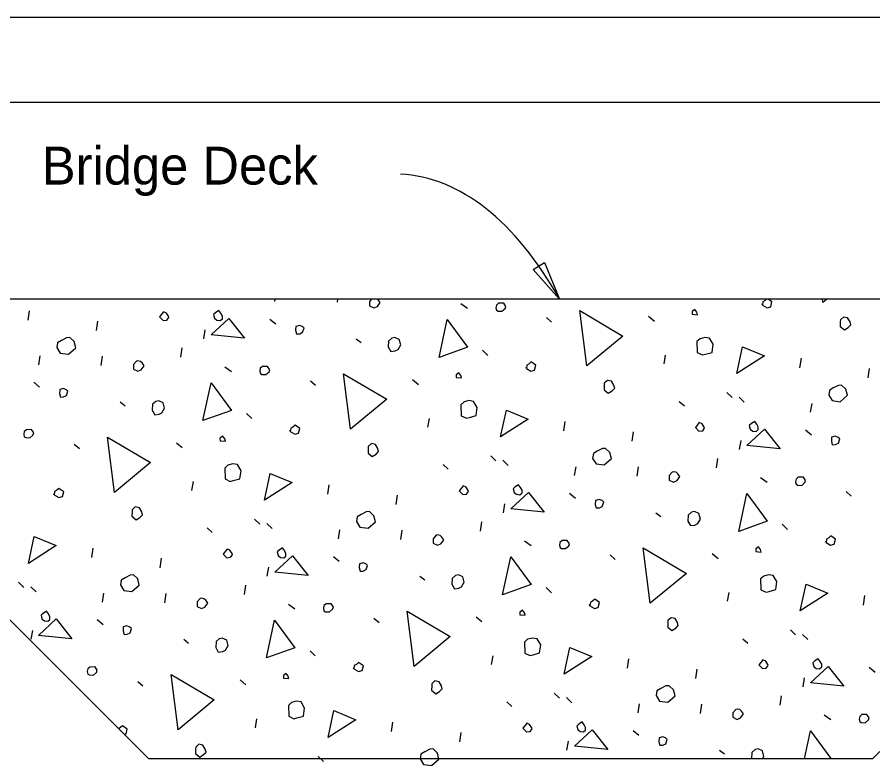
# Model space of a CAD drawing. Extents: x 0 to 30.8, y 0 to 21.2.
# Drawn here: x 22.102 to 25.516, y 16.841 to 19.8 of the extents above; entities that cross this region are included whole.
import ezdxf

# ---------------------------------------------------------------- set-up
doc = ezdxf.new("R2010")
doc.units = 0
for name, color, linetype in [('ActivePts-ConstElements', 7, 'Continuous'), ('Dimension', 7, 'Continuous'), ('Miscellaneous', 7, 'Continuous'), ('Miscellaneous1', 7, 'Continuous'), ('SupstrConc', 7, 'Continuous'), ('TextStructures', 7, 'Continuous')]:
    doc.layers.add(name, color=color, linetype=linetype)

msp = doc.modelspace()

# ---------------------------------------------------------------- linework, layer by layer
at = {"layer": 'ActivePts-ConstElements'}
msp.add_lwpolyline([(0, 0), (30.7879, 0), (30.7879, 19.4596), (0, 19.4596)], close=True, dxfattribs=at)
at = {"layer": 'Dimension'}
msp.add_lwpolyline([(24.2661, 18.6746), (24.1614, 18.7936), (24.2064, 18.8214)], close=True, dxfattribs=at)
msp.add_ellipse((23.5209, 16.8059), major_axis=(-0.1111, -2.3674), ratio=0.464296, start_param=2.502126, end_param=3.141581, dxfattribs=at)
at = {"layer": 'Miscellaneous'}
for p, q in [((23.1306, 18.6659), (23.1321, 18.6747)), ((23.3799, 18.6628), (23.3816, 18.6747)), ((23.873, 18.6577), (23.8988, 18.6388)), ((22.1464, 18.5911), (22.1518, 18.6288)), ((24.6216, 18.6073), (24.6449, 18.5876)), ((22.4188, 18.5502), (22.4242, 18.5879)), ((23.1105, 18.5958), (23.1339, 18.5762)), ((24.2141, 18.6016), (24.2345, 18.5838)), ((22.8469, 18.5174), (22.8529, 18.5526)), ((23.4551, 18.5173), (23.4748, 18.5019)), ((22.7553, 18.4437), (22.7607, 18.4814)), ((23.9592, 18.4712), (23.9802, 18.4509)), ((22.1888, 18.4135), (22.1949, 18.4488)), ((22.4381, 18.4104), (22.4435, 18.4481)), ((24.683, 18.4167), (24.6891, 18.4519)), ((25.2254, 18.4015), (25.2308, 18.4392)), ((22.9312, 18.4054), (22.957, 18.3864)), ((25.4978, 18.3606), (25.5032, 18.3983)), ((22.1688, 18.3434), (22.1921, 18.3238)), ((23.2724, 18.3493), (23.2927, 18.3314)), ((23.6798, 18.3549), (23.7032, 18.3353)), ((24.9335, 18.3026), (24.9545, 18.2824)), ((22.5133, 18.2649), (22.533, 18.2495)), ((24.7437, 18.2673), (24.764, 18.2494)), ((24.9824, 18.2846), (25.0033, 18.2644)), ((25.2678, 18.224), (25.2739, 18.2592)), ((23.0174, 18.2188), (23.0384, 18.1986)), ((23.7412, 18.1643), (23.7473, 18.1996)), ((24.2836, 18.1492), (24.289, 18.1869)), ((24.556, 18.1083), (24.5614, 18.146)), ((25.2477, 18.1539), (25.2711, 18.1343)), ((22.3306, 18.0969), (22.3509, 18.0791)), ((22.738, 18.1026), (22.7614, 18.0829)), ((24.9841, 18.0755), (24.9901, 18.1107)), ((23.9918, 18.0503), (24.0127, 18.03)), ((24.0406, 18.0323), (24.0615, 18.012)), ((24.8925, 18.0018), (24.8979, 18.0394)), ((23.8019, 18.0149), (23.8223, 17.9971)), ((24.326, 17.9716), (24.3321, 18.0069)), ((24.5753, 17.9685), (24.5807, 18.0062)), ((25.0684, 17.9635), (25.0942, 17.9445)), ((22.7994, 17.912), (22.8055, 17.9472)), ((23.3418, 17.8968), (23.3473, 17.9345)), ((23.6142, 17.8559), (23.6196, 17.8936)), ((24.306, 17.9015), (24.3293, 17.8819)), ((25.4096, 17.9074), (25.4299, 17.8895)), ((24.0423, 17.8231), (24.0484, 17.8584)), ((24.6505, 17.823), (24.6702, 17.8076)), ((23.05, 17.7979), (23.0709, 17.7777)), ((23.9507, 17.7494), (23.9562, 17.7871)), ((22.8602, 17.7626), (22.8805, 17.7447)), ((23.0988, 17.7799), (23.1198, 17.7597)), ((23.3842, 17.7193), (23.3903, 17.7545)), ((23.6335, 17.7162), (23.639, 17.7539)), ((25.1546, 17.7769), (25.1756, 17.7567)), ((24.1266, 17.7111), (24.1524, 17.6922)), ((22.4001, 17.6445), (22.4055, 17.6822)), ((23.3642, 17.6492), (23.3876, 17.6296)), ((24.4678, 17.655), (24.4881, 17.6372)), ((24.8752, 17.6607), (24.8986, 17.641)), ((22.6724, 17.6036), (22.6778, 17.6413)), ((23.1005, 17.5708), (23.1066, 17.606)), ((23.7087, 17.5707), (23.7284, 17.5552)), ((22.1082, 17.5456), (22.1292, 17.5253)), ((22.157, 17.5276), (22.178, 17.5073)), ((23.009, 17.4971), (23.0144, 17.5347)), ((24.2129, 17.5246), (24.2338, 17.5043)), ((22.4425, 17.4669), (22.4485, 17.5022)), ((22.6918, 17.4638), (22.6972, 17.5015)), ((24.9366, 17.4701), (24.9427, 17.5053)), ((25.479, 17.4549), (25.4845, 17.4926)), ((23.1849, 17.4588), (23.2106, 17.4398)), ((22.4224, 17.3968), (22.4458, 17.3772)), ((23.526, 17.4027), (23.5463, 17.3848)), ((23.9334, 17.4083), (23.9568, 17.3887)), ((22.1587, 17.3184), (22.1648, 17.3537)), ((25.1872, 17.356), (25.2081, 17.3358)), ((22.767, 17.3183), (22.7866, 17.3029)), ((24.9974, 17.3207), (25.0177, 17.3028)), ((25.236, 17.338), (25.257, 17.3178)), ((23.2711, 17.2722), (23.292, 17.252)), ((23.9949, 17.2177), (24.0009, 17.253)), ((24.5373, 17.2026), (24.5427, 17.2403)), ((25.5014, 17.2073), (25.5248, 17.1877)), ((24.8096, 17.1617), (24.815, 17.1994)), ((22.5842, 17.1503), (22.6045, 17.1325)), ((22.9917, 17.156), (23.015, 17.1363)), ((25.2377, 17.1289), (25.2438, 17.1641)), ((24.2454, 17.1037), (24.2664, 17.0834)), ((24.2942, 17.0857), (24.3152, 17.0654)), ((25.1462, 17.0551), (25.1516, 17.0928)), ((24.0556, 17.0683), (24.0759, 17.0505)), ((24.5797, 17.025), (24.5857, 17.0603)), ((24.8289, 17.0219), (24.8344, 17.0596)), ((23.0531, 16.9654), (23.0592, 17.0006)), ((25.3221, 17.0169), (25.3478, 16.9979)), ((23.5955, 16.9502), (23.6009, 16.9879)), ((23.8678, 16.9093), (23.8733, 16.947)), ((24.5596, 16.9549), (24.583, 16.9353)), ((24.2959, 16.8765), (24.302, 16.9118)), ((24.9042, 16.8764), (24.9238, 16.861)), ((23.3036, 16.8513), (23.3246, 16.8311))]:
    msp.add_line(p, q, dxfattribs=at)
for points in [[(23.5084, 18.6662), (23.5081, 18.648), (23.5258, 18.6398), (23.5397, 18.6461), (23.5509, 18.662), (23.5428, 18.6728), (23.5406, 18.6747)], [(23.5159, 18.6747), (23.5084, 18.6662)], [(25.092, 18.6747), (25.0862, 18.6697), (25.0772, 18.6647), (25.0756, 18.6513), (25.0743, 18.6561)], [(25.0756, 18.6513), (25.094, 18.6407), (25.1085, 18.6446), (25.1136, 18.6641), (25.098, 18.6747)], [(25.3162, 18.6614), (25.3145, 18.6747)], [(25.3324, 18.6747), (25.3162, 18.6614)], [(24.0147, 18.631), (24.0209, 18.6275), (24.0366, 18.6265), (24.0492, 18.6377), (24.0521, 18.6462), (24.0434, 18.6594), (24.0228, 18.659), (24.0144, 18.6516), (24.0122, 18.6407), (24.0147, 18.631)], [(22.6707, 18.6048), (22.6849, 18.5904), (22.7001, 18.5919), (22.7078, 18.6017), (22.7065, 18.6066), (22.6978, 18.6198), (22.6862, 18.6244), (22.6785, 18.6146), (22.6707, 18.6048)], [(22.8898, 18.5987), (22.8996, 18.591), (22.913, 18.5894), (22.9213, 18.5968), (22.9212, 18.6072), (22.9155, 18.6186), (22.9074, 18.6294), (22.8942, 18.6207), (22.8859, 18.6132), (22.8898, 18.5987)], [(24.3744, 18.409), (24.3465, 18.6293), (24.5186, 18.5279), (24.3744, 18.409)], [(24.7955, 18.615), (24.8167, 18.613), (24.8141, 18.6226), (24.8061, 18.6334), (24.7953, 18.6253), (24.7955, 18.615)], [(22.8763, 18.533), (22.9468, 18.5985), (23.0093, 18.5195), (22.8763, 18.533)], [(23.7856, 18.4428), (23.8177, 18.5937), (23.899, 18.4835), (23.7856, 18.4428)], [(25.386, 18.5843), (25.3857, 18.5661), (25.4023, 18.5525), (25.418, 18.5618), (25.4281, 18.5723), (25.4249, 18.5844), (25.4155, 18.6), (25.3991, 18.6034), (25.3865, 18.5922), (25.386, 18.5843)], [(23.2132, 18.5508), (23.2171, 18.5363), (23.2298, 18.5372), (23.2412, 18.5428), (23.247, 18.5599), (23.2402, 18.5658), (23.2286, 18.5705), (23.2141, 18.5666), (23.2132, 18.5508)], [(22.261, 18.482), (22.2748, 18.4598), (22.307, 18.4555), (22.3362, 18.4815), (22.3298, 18.5056), (22.3125, 18.5217), (22.2998, 18.5209), (22.2794, 18.5102), (22.2638, 18.5009), (22.261, 18.482)], [(23.5844, 18.5079), (23.583, 18.4843), (23.593, 18.4662), (23.6106, 18.4684), (23.622, 18.474), (23.6326, 18.4924), (23.6268, 18.5141), (23.6091, 18.5223), (23.597, 18.5191), (23.5844, 18.5079)], [(24.8143, 18.5062), (24.8156, 18.4626), (24.8364, 18.4526), (24.8485, 18.4558), (24.8751, 18.4629), (24.8794, 18.4952), (24.865, 18.5198), (24.8462, 18.5225), (24.8268, 18.5173), (24.8143, 18.5062)], [(24.9729, 18.3779), (24.996, 18.485), (25.0833, 18.4489), (24.9729, 18.3779)], [(22.5666, 18.4138), (22.5663, 18.3956), (22.584, 18.3874), (22.5979, 18.3937), (22.6091, 18.4097), (22.6011, 18.4205), (22.5943, 18.4264), (22.5833, 18.4286), (22.5785, 18.4273), (22.5666, 18.4138)], [(23.073, 18.3787), (23.0791, 18.3751), (23.0949, 18.3742), (23.1074, 18.3853), (23.1103, 18.3938), (23.1016, 18.407), (23.081, 18.4067), (23.0726, 18.3993), (23.0704, 18.3883), (23.073, 18.3787)], [(24.1339, 18.3989), (24.1522, 18.3883), (24.1667, 18.3922), (24.1719, 18.4117), (24.1528, 18.4247), (24.1445, 18.4173), (24.1355, 18.4123), (24.1339, 18.3989), (24.1326, 18.4038)], [(23.4327, 18.1567), (23.4047, 18.377), (23.5768, 18.2756), (23.4327, 18.1567)], [(23.8537, 18.3627), (23.875, 18.3606), (23.8724, 18.3703), (23.8643, 18.3811), (23.8535, 18.373), (23.8537, 18.3627)], [(22.8439, 18.1905), (22.8759, 18.3414), (22.9572, 18.2312), (22.8439, 18.1905)], [(24.4443, 18.332), (24.444, 18.3138), (24.4606, 18.3001), (24.4762, 18.3095), (24.4863, 18.32), (24.4831, 18.332), (24.4737, 18.3476), (24.4573, 18.351), (24.4447, 18.3399), (24.4443, 18.332)], [(25.34, 18.2925), (25.3537, 18.2703), (25.3859, 18.266), (25.4152, 18.2919), (25.4088, 18.3161), (25.3915, 18.3322), (25.3788, 18.3313), (25.3583, 18.3207), (25.3427, 18.3113), (25.34, 18.2925)], [(22.2714, 18.2985), (22.2753, 18.284), (22.288, 18.2848), (22.2994, 18.2905), (22.3052, 18.3075), (22.2984, 18.3135), (22.2868, 18.3181), (22.2724, 18.3143), (22.2714, 18.2985)], [(22.6427, 18.2556), (22.6412, 18.2319), (22.6512, 18.2139), (22.6688, 18.216), (22.6802, 18.2217), (22.6908, 18.24), (22.685, 18.2618), (22.6673, 18.27), (22.6552, 18.2667), (22.6427, 18.2556)], [(23.8725, 18.2538), (23.8739, 18.2102), (23.8946, 18.2002), (23.9067, 18.2035), (23.9333, 18.2106), (23.9376, 18.2428), (23.9232, 18.2674), (23.9044, 18.2702), (23.8851, 18.265), (23.8725, 18.2538)], [(24.0311, 18.1255), (24.0542, 18.2326), (24.1415, 18.1965), (24.0311, 18.1255)], [(23.1921, 18.1466), (23.2105, 18.136), (23.2249, 18.1399), (23.2301, 18.1594), (23.2111, 18.1724), (23.2027, 18.165), (23.1937, 18.16), (23.1921, 18.1466), (23.1908, 18.1514)], [(24.8079, 18.1629), (24.8221, 18.1485), (24.8373, 18.15), (24.845, 18.1598), (24.8437, 18.1647), (24.835, 18.1779), (24.8234, 18.1825), (24.8157, 18.1727), (24.8079, 18.1629)], [(25.027, 18.1568), (25.0368, 18.1491), (25.0502, 18.1475), (25.0585, 18.1549), (25.0583, 18.1652), (25.0527, 18.1767), (25.0446, 18.1875), (25.0314, 18.1787), (25.0231, 18.1713), (25.027, 18.1568)], [(22.1312, 18.1263), (22.1373, 18.1228), (22.1531, 18.1218), (22.1656, 18.133), (22.1685, 18.1415), (22.1598, 18.1547), (22.1392, 18.1543), (22.1308, 18.1469), (22.1286, 18.136), (22.1312, 18.1263)], [(22.9119, 18.1103), (22.9332, 18.1083), (22.9306, 18.1179), (22.9225, 18.1287), (22.9117, 18.1206), (22.9119, 18.1103)], [(25.0135, 18.0911), (25.084, 18.1566), (25.1465, 18.0776), (25.0135, 18.0911)], [(25.3504, 18.1089), (25.3543, 18.0944), (25.367, 18.0952), (25.3784, 18.1009), (25.3842, 18.118), (25.3774, 18.1239), (25.3658, 18.1286), (25.3513, 18.1247), (25.3504, 18.1089)], [(22.4909, 17.9043), (22.4629, 18.1246), (22.635, 18.0232), (22.4909, 17.9043)], [(23.5025, 18.0796), (23.5022, 18.0614), (23.5188, 18.0478), (23.5344, 18.0571), (23.5445, 18.0676), (23.5413, 18.0797), (23.5319, 18.0953), (23.5155, 18.0987), (23.503, 18.0875), (23.5025, 18.0796)], [(24.3982, 18.0401), (24.412, 18.0179), (24.4442, 18.0136), (24.4734, 18.0396), (24.467, 18.0637), (24.4497, 18.0798), (24.437, 18.079), (24.4166, 18.0683), (24.401, 18.059), (24.3982, 18.0401)], [(22.9307, 18.0015), (22.9321, 17.9579), (22.9529, 17.9479), (22.9649, 17.9511), (22.9915, 17.9583), (22.9958, 17.9905), (22.9814, 18.0151), (22.9626, 18.0178), (22.9433, 18.0126), (22.9307, 18.0015)], [(23.0893, 17.8732), (23.1124, 17.9803), (23.1997, 17.9442), (23.0893, 17.8732)], [(24.7038, 17.9719), (24.7035, 17.9537), (24.7212, 17.9455), (24.7351, 17.9518), (24.7463, 17.9678), (24.7383, 17.9785), (24.7315, 17.9845), (24.7205, 17.9867), (24.7157, 17.9854), (24.7038, 17.9719)], [(25.2102, 17.9368), (25.2163, 17.9332), (25.2321, 17.9323), (25.2446, 17.9434), (25.2475, 17.9519), (25.2388, 17.9651), (25.2182, 17.9648), (25.2098, 17.9574), (25.2076, 17.9464), (25.2102, 17.9368)], [(23.8662, 17.9105), (23.8803, 17.8962), (23.8955, 17.8977), (23.9032, 17.9075), (23.9019, 17.9123), (23.8932, 17.9255), (23.8816, 17.9302), (23.8739, 17.9203), (23.8662, 17.9105)], [(24.0852, 17.9045), (24.095, 17.8968), (24.1084, 17.8952), (24.1167, 17.9026), (24.1166, 17.9129), (24.1109, 17.9243), (24.1029, 17.9351), (24.0897, 17.9264), (24.0813, 17.919), (24.0852, 17.9045)], [(22.2503, 17.8942), (22.2687, 17.8836), (22.2832, 17.8875), (22.2883, 17.907), (22.2693, 17.92), (22.2609, 17.9126), (22.2519, 17.9076), (22.2503, 17.8942), (22.249, 17.8991)], [(24.0717, 17.8388), (24.1422, 17.9042), (24.2048, 17.8252), (24.0717, 17.8388)], [(24.9811, 17.7485), (25.0131, 17.8995), (25.0944, 17.7893), (24.9811, 17.7485)], [(24.4086, 17.8566), (24.4125, 17.8421), (24.4252, 17.8429), (24.4366, 17.8485), (24.4424, 17.8656), (24.4356, 17.8716), (24.424, 17.8762), (24.4096, 17.8723), (24.4086, 17.8566)], [(22.5607, 17.8273), (22.5604, 17.8091), (22.577, 17.7954), (22.5926, 17.8048), (22.6028, 17.8153), (22.5995, 17.8273), (22.5902, 17.843), (22.5737, 17.8463), (22.5612, 17.8352), (22.5607, 17.8273)], [(23.4565, 17.7878), (23.4702, 17.7656), (23.5024, 17.7613), (23.5317, 17.7872), (23.5252, 17.8114), (23.5079, 17.8275), (23.4952, 17.8266), (23.4748, 17.816), (23.4592, 17.8066), (23.4565, 17.7878)], [(24.7799, 17.8137), (24.7784, 17.79), (24.7884, 17.772), (24.806, 17.7741), (24.8174, 17.7798), (24.828, 17.7981), (24.8222, 17.8199), (24.8045, 17.828), (24.7924, 17.8248), (24.7799, 17.8137)], [(22.1476, 17.6208), (22.1706, 17.7279), (22.258, 17.6918), (22.1476, 17.6208)], [(23.762, 17.7195), (23.7617, 17.7013), (23.7795, 17.6932), (23.7933, 17.6995), (23.8046, 17.7154), (23.7965, 17.7262), (23.7897, 17.7321), (23.7788, 17.7344), (23.7739, 17.7331), (23.762, 17.7195)], [(25.3293, 17.7047), (25.3477, 17.6941), (25.3621, 17.698), (25.3673, 17.7174), (25.3483, 17.7305), (25.3399, 17.723), (25.3309, 17.718), (25.3293, 17.7047), (25.328, 17.7095)], [(24.2684, 17.6844), (24.2745, 17.6809), (24.2903, 17.6799), (24.3028, 17.691), (24.3057, 17.6996), (24.297, 17.7128), (24.2764, 17.7124), (24.268, 17.705), (24.2658, 17.6941), (24.2684, 17.6844)], [(25.0491, 17.6684), (25.0704, 17.6664), (25.0678, 17.676), (25.0597, 17.6868), (25.0489, 17.6787), (25.0491, 17.6684)], [(22.9244, 17.6582), (22.9386, 17.6438), (22.9537, 17.6453), (22.9614, 17.6551), (22.9601, 17.66), (22.9514, 17.6732), (22.9398, 17.6778), (22.9321, 17.668), (22.9244, 17.6582)], [(23.13, 17.5864), (23.2004, 17.6519), (23.263, 17.5729), (23.13, 17.5864)], [(23.1434, 17.6521), (23.1532, 17.6444), (23.1666, 17.6428), (23.175, 17.6502), (23.1748, 17.6605), (23.1691, 17.672), (23.1611, 17.6828), (23.1479, 17.674), (23.1395, 17.6666), (23.1434, 17.6521)], [(24.6281, 17.4624), (24.6001, 17.6827), (24.7722, 17.5813), (24.6281, 17.4624)], [(23.4668, 17.6042), (23.4707, 17.5897), (23.4834, 17.5905), (23.4949, 17.5962), (23.5006, 17.6133), (23.4939, 17.6192), (23.4823, 17.6239), (23.4678, 17.62), (23.4668, 17.6042)], [(24.0393, 17.4962), (24.0713, 17.6471), (24.1526, 17.5369), (24.0393, 17.4962)], [(22.5147, 17.5354), (22.5284, 17.5132), (22.5606, 17.5089), (22.5899, 17.5349), (22.5834, 17.559), (22.5662, 17.5751), (22.5534, 17.5743), (22.533, 17.5636), (22.5174, 17.5543), (22.5147, 17.5354)], [(23.8381, 17.5613), (23.8367, 17.5377), (23.8467, 17.5196), (23.8642, 17.5218), (23.8756, 17.5274), (23.8862, 17.5458), (23.8804, 17.5675), (23.8627, 17.5757), (23.8506, 17.5725), (23.8381, 17.5613)], [(25.0679, 17.5596), (25.0693, 17.5159), (25.0901, 17.506), (25.1021, 17.5092), (25.1287, 17.5163), (25.133, 17.5486), (25.1186, 17.5732), (25.0998, 17.5759), (25.0805, 17.5707), (25.0679, 17.5596)], [(25.2265, 17.4313), (25.2496, 17.5384), (25.3369, 17.5023), (25.2265, 17.4313)], [(22.8203, 17.4672), (22.82, 17.449), (22.8377, 17.4408), (22.8515, 17.4471), (22.8628, 17.4631), (22.8547, 17.4738), (22.8479, 17.4798), (22.837, 17.482), (22.8322, 17.4807), (22.8203, 17.4672)], [(23.3266, 17.4321), (23.3327, 17.4285), (23.3485, 17.4276), (23.3611, 17.4387), (23.3639, 17.4472), (23.3552, 17.4604), (23.3346, 17.4601), (23.3263, 17.4527), (23.324, 17.4417), (23.3266, 17.4321)], [(24.3875, 17.4523), (24.4059, 17.4417), (24.4204, 17.4456), (24.4255, 17.4651), (24.4065, 17.4781), (24.3981, 17.4707), (24.3891, 17.4657), (24.3875, 17.4523), (24.3862, 17.4572)], [(22.2016, 17.3998), (22.2115, 17.3921), (22.2248, 17.3905), (22.2332, 17.3979), (22.233, 17.4082), (22.2274, 17.4196), (22.2193, 17.4304), (22.2061, 17.4217), (22.1977, 17.4143), (22.2016, 17.3998)], [(23.6863, 17.2101), (23.6583, 17.4304), (23.8305, 17.3289), (23.6863, 17.2101)], [(24.1073, 17.4161), (24.1286, 17.414), (24.126, 17.4237), (24.1179, 17.4345), (24.1072, 17.4264), (24.1073, 17.4161)], [(22.1882, 17.3341), (22.2586, 17.3995), (22.3212, 17.3205), (22.1882, 17.3341)], [(23.0975, 17.2438), (23.1295, 17.3948), (23.2108, 17.2846), (23.0975, 17.2438)], [(24.6979, 17.3854), (24.6976, 17.3672), (24.7142, 17.3535), (24.7298, 17.3629), (24.74, 17.3734), (24.7367, 17.3854), (24.7274, 17.401), (24.7109, 17.4044), (24.6984, 17.3933), (24.6979, 17.3854)], [(22.525, 17.3519), (22.5289, 17.3374), (22.5417, 17.3382), (22.5531, 17.3438), (22.5589, 17.3609), (22.5521, 17.3669), (22.5405, 17.3715), (22.526, 17.3676), (22.525, 17.3519)], [(22.8963, 17.309), (22.8949, 17.2853), (22.9049, 17.2673), (22.9224, 17.2694), (22.9339, 17.2751), (22.9445, 17.2934), (22.9386, 17.3152), (22.9209, 17.3234), (22.9088, 17.3201), (22.8963, 17.309)], [(24.1262, 17.3072), (24.1275, 17.2636), (24.1483, 17.2536), (24.1604, 17.2569), (24.1869, 17.264), (24.1912, 17.2962), (24.1769, 17.3208), (24.158, 17.3235), (24.1387, 17.3184), (24.1262, 17.3072)], [(24.2848, 17.1789), (24.3078, 17.286), (24.3952, 17.2499), (24.2848, 17.1789)], [(25.2806, 17.2102), (25.2904, 17.2025), (25.3038, 17.2009), (25.3122, 17.2083), (25.312, 17.2186), (25.3063, 17.2301), (25.2983, 17.2408), (25.2851, 17.2321), (25.2767, 17.2247), (25.2806, 17.2102)], [(22.3848, 17.1797), (22.391, 17.1762), (22.4067, 17.1752), (22.4193, 17.1863), (22.4222, 17.1949), (22.4135, 17.2081), (22.3928, 17.2077), (22.3845, 17.2003), (22.3822, 17.1894), (22.3848, 17.1797)], [(23.4457, 17.2), (23.4641, 17.1894), (23.4786, 17.1933), (23.4837, 17.2127), (23.4647, 17.2258), (23.4563, 17.2183), (23.4473, 17.2133), (23.4457, 17.2), (23.4444, 17.2048)], [(25.0616, 17.2162), (25.0758, 17.2019), (25.0909, 17.2034), (25.0986, 17.2132), (25.0973, 17.2181), (25.0886, 17.2313), (25.077, 17.2359), (25.0693, 17.2261), (25.0616, 17.2162)], [(25.2672, 17.1445), (25.3376, 17.21), (25.4002, 17.131), (25.2672, 17.1445)], [(22.7445, 16.9577), (22.7166, 17.178), (22.8887, 17.0766), (22.7445, 16.9577)], [(23.1656, 17.1637), (23.1868, 17.1617), (23.1842, 17.1713), (23.1762, 17.1821), (23.1654, 17.174), (23.1656, 17.1637)], [(23.7561, 17.133), (23.7558, 17.1148), (23.7724, 17.1012), (23.788, 17.1105), (23.7982, 17.121), (23.7949, 17.1331), (23.7856, 17.1487), (23.7692, 17.1521), (23.7566, 17.1409), (23.7561, 17.133)], [(24.6519, 17.0935), (24.6656, 17.0713), (24.6978, 17.067), (24.7271, 17.093), (24.7206, 17.1171), (24.7034, 17.1332), (24.6906, 17.1324), (24.6702, 17.1217), (24.6546, 17.1124), (24.6519, 17.0935)], [(23.1844, 17.0549), (23.1857, 17.0113), (23.2065, 17.0013), (23.2186, 17.0045), (23.2451, 17.0116), (23.2494, 17.0439), (23.2351, 17.0685), (23.2162, 17.0712), (23.1969, 17.066), (23.1844, 17.0549)], [(24.9575, 17.0253), (24.9572, 17.0071), (24.9749, 16.9989), (24.9887, 17.0052), (25, 17.0212), (24.9919, 17.0319), (24.9851, 17.0379), (24.9742, 17.0401), (24.9694, 17.0388), (24.9575, 17.0253)], [(23.343, 16.9266), (23.3661, 17.0337), (23.4534, 16.9976), (23.343, 16.9266)], [(25.4638, 16.9901), (25.4699, 16.9866), (25.4857, 16.9857), (25.4983, 16.9968), (25.5011, 17.0053), (25.4924, 17.0185), (25.4718, 17.0182), (25.4635, 17.0108), (25.4612, 16.9998), (25.4638, 16.9901)], [(22.5297, 16.939), (22.5368, 16.9409), (22.5419, 16.9604), (22.5229, 16.9734), (22.5146, 16.966), (22.5069, 16.9618)], [(24.1198, 16.9639), (24.134, 16.9496), (24.1491, 16.951), (24.1568, 16.9609), (24.1555, 16.9657), (24.1468, 16.9789), (24.1352, 16.9836), (24.1275, 16.9737), (24.1198, 16.9639)], [(24.3388, 16.9579), (24.3487, 16.9502), (24.362, 16.9486), (24.3704, 16.956), (24.3702, 16.9663), (24.3646, 16.9777), (24.3565, 16.9885), (24.3433, 16.9798), (24.3349, 16.9724), (24.3388, 16.9579)], [(24.3254, 16.8922), (24.3958, 16.9576), (24.4584, 16.8786), (24.3254, 16.8922)], [(25.2431, 16.8414), (25.2667, 16.9529), (25.348, 16.8427), (25.3446, 16.8414)], [(22.8144, 16.8807), (22.8141, 16.8625), (22.8307, 16.8488), (22.8463, 16.8582), (22.8564, 16.8687), (22.8532, 16.8807), (22.8438, 16.8963), (22.8274, 16.8997), (22.8148, 16.8886), (22.8144, 16.8807)], [(24.6622, 16.91), (24.6661, 16.8955), (24.6788, 16.8963), (24.6903, 16.9019), (24.6961, 16.919), (24.6893, 16.925), (24.6777, 16.9296), (24.6632, 16.9257), (24.6622, 16.91)], [(23.7101, 16.8412), (23.7238, 16.819), (23.756, 16.8147), (23.7853, 16.8406), (23.7788, 16.8648), (23.7616, 16.8809), (23.7489, 16.88), (23.7284, 16.8694), (23.7128, 16.86), (23.7101, 16.8412)], [(25.0335, 16.8671), (25.0321, 16.8434), (25.0332, 16.8414)], [(25.0758, 16.8414), (25.0817, 16.8515), (25.0758, 16.8732), (25.0581, 16.8814), (25.046, 16.8782), (25.0335, 16.8671)]]:
    msp.add_lwpolyline(points, dxfattribs=at)
at = {"layer": 'Miscellaneous1'}
msp.add_lwpolyline([(0, 19.8), (30.8, 19.8), (30.8, 0), (0, 0)], close=True, dxfattribs=at)
at = {"layer": 'SupstrConc'}
for p, q in [((25.794, 18.6747), (21.0171, 18.6747)), ((22.6273, 16.8414), (21.7523, 17.7164)), ((25.5146, 16.8414), (25.544, 16.8709)), ((25.5146, 16.8414), (22.6273, 16.8414))]:
    msp.add_line(p, q, dxfattribs=at)

# ---------------------------------------------------------------- texts
at = {"layer": 'TextStructures'}
msp.add_text('Bridge Deck', height=0.1512, dxfattribs=at).set_placement((22.2008, 19.132))

doc.saveas('drawing.dxf')
